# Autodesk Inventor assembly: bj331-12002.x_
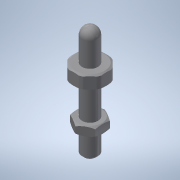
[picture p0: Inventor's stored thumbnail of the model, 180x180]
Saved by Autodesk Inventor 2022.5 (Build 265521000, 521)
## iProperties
Part Number: bj331-12002.x_
Material: 一般
Document SubType Name: Assembly
Designer: ImaoCorp
Sending System: SOLIDWORKS 2017-2017317
MC: AMD64
MC_MODEL: Intel64 Family 6 Model 60 Stepping 3, GenuineIntel
OS: Windows_NT
FRU: Parasolid Version 29.0, build 201,  4-17-2017
FORMAT: text
GUISE: transmit
KEY: bj331-12002
FILE: bj331-12002.x_t
DATE: Fri Mar 15 10:14:22 2019
Author: ImaoCorp
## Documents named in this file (3)
- X:\14_SW2022-Inv2022\00_全2023-1023新製品(TCC)まで\b\bj331-12002\BJ331-12002.iam
- X:\14_SW2022-Inv2022\00_全2023-1023新製品(TCC)まで\b\bj331-12002\bj331-12002_01.ipt
- X:\14_SW2022-Inv2022\00_全2023-1023新製品(TCC)まで\b\bj331-12002\bj331-12002_02.ipt
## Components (2 placed, 2 different names)
1. bj331-12002_01
2. bj331-12002_02
